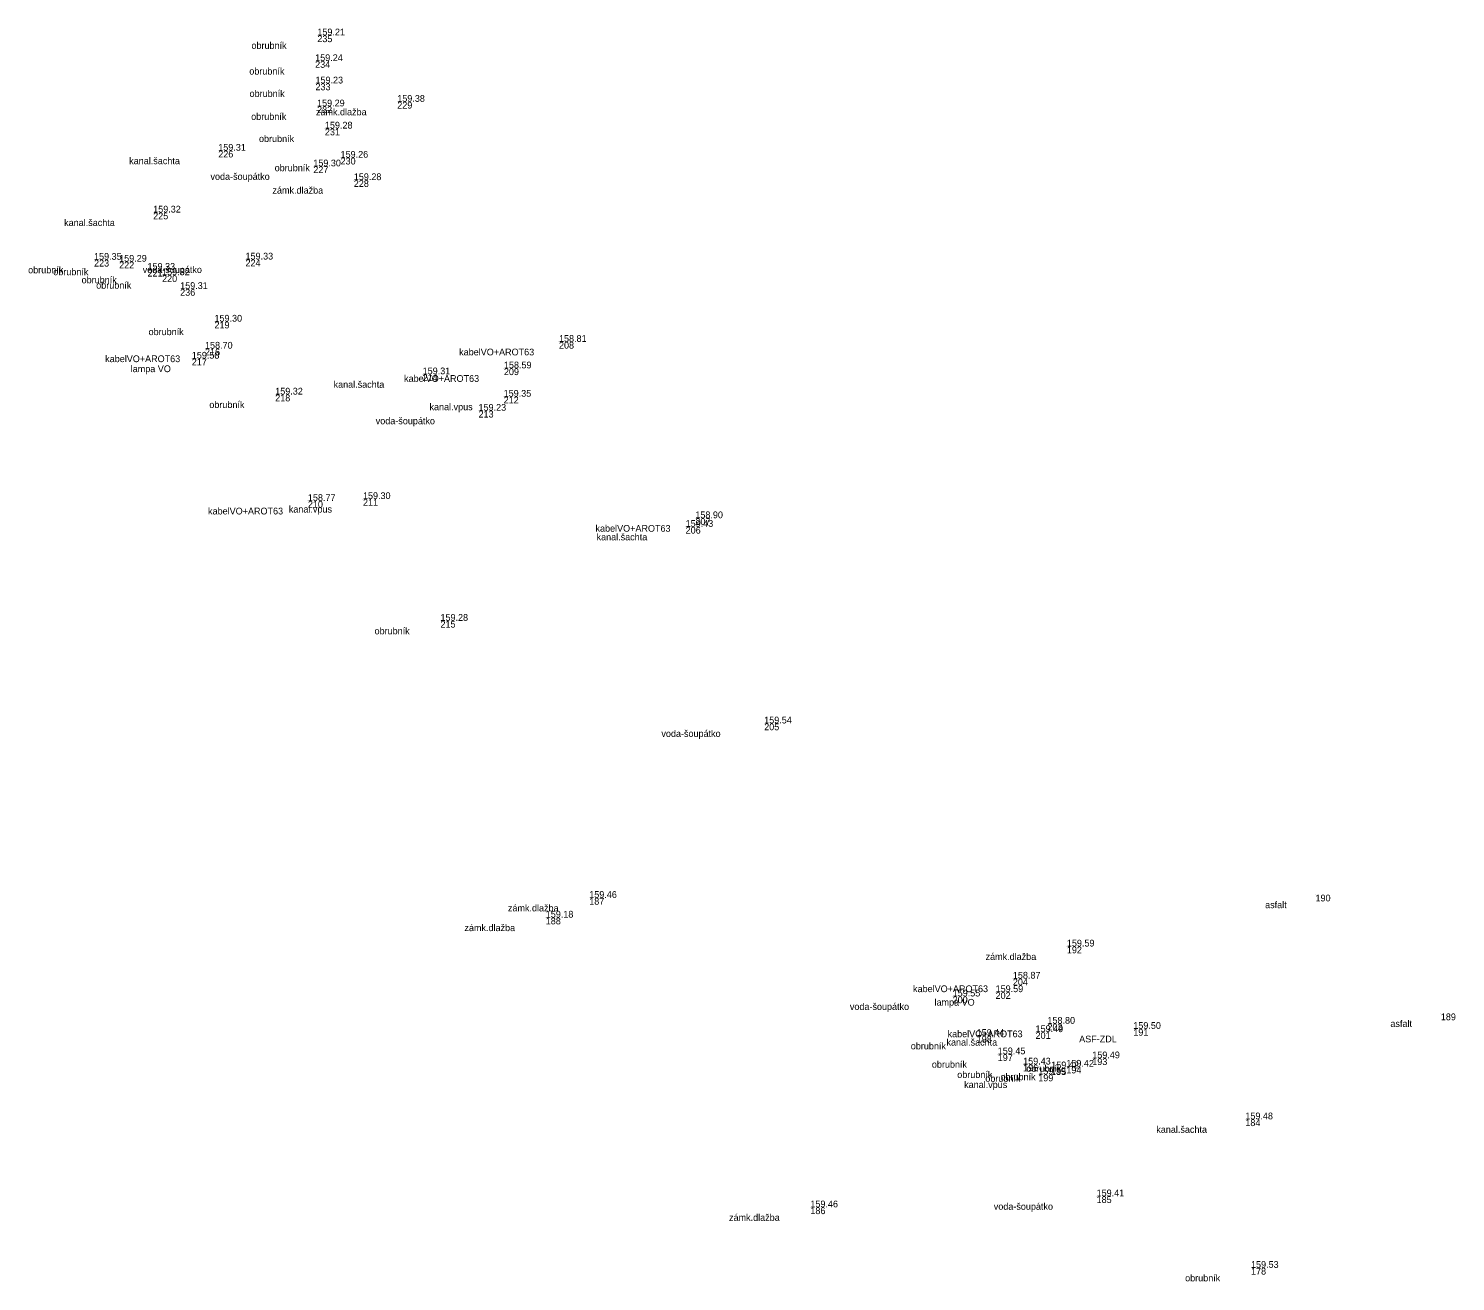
# Model space of a CAD drawing. Extents: x -583304 to -583163, y -1211038 to -1210841.
# Drawn here: x -583304.3 to -583251.4, y -1210887.3 to -1210840.9 of the extents above; entities that cross this region are included whole.
import ezdxf

# ---------------------------------------------------------------- set-up
doc = ezdxf.new("R2010")
doc.units = 0
for name, color, linetype in [('Vrstva 10', 7, 'Continuous'), ('Vrstva 7', 7, 'Continuous'), ('Vrstva 8', 7, 'Continuous'), ('Vrstva 9', 7, 'Continuous')]:
    doc.layers.add(name, color=color, linetype=linetype)

msp = doc.modelspace()

# ---------------------------------------------------------------- linework, layer by layer
at = {"layer": 'Vrstva 7'}
for p, q in [((-583293.57, -1210841.14), (-583293.57, -1210841.14)), ((-583293.65, -1210842.09), (-583293.65, -1210842.09)), ((-583293.64, -1210842.92), (-583293.64, -1210842.92)), ((-583290.61, -1210843.6), (-583290.61, -1210843.6)), ((-583293.58, -1210843.77), (-583293.58, -1210843.77)), ((-583293.29, -1210844.59), (-583293.29, -1210844.59)), ((-583297.24, -1210845.41), (-583297.24, -1210845.41)), ((-583292.71, -1210845.67), (-583292.71, -1210845.67)), ((-583293.72, -1210845.99), (-583293.72, -1210845.99)), ((-583292.22, -1210846.5), (-583292.22, -1210846.5)), ((-583299.65, -1210847.7), (-583299.65, -1210847.7)), ((-583296.23, -1210849.44), (-583296.23, -1210849.44)), ((-583301.84, -1210849.45), (-583301.84, -1210849.45)), ((-583300.91, -1210849.52), (-583300.91, -1210849.52)), ((-583299.86, -1210849.82), (-583299.86, -1210849.82)), ((-583299.32, -1210850.02), (-583299.32, -1210850.02)), ((-583298.65, -1210850.53), (-583298.65, -1210850.53)), ((-583297.38, -1210851.74), (-583297.38, -1210851.74)), ((-583284.62, -1210852.49), (-583284.62, -1210852.49)), ((-583298.22, -1210853.11), (-583298.22, -1210853.11)), ((-583297.73, -1210852.74), (-583297.73, -1210852.74)), ((-583286.66, -1210853.47), (-583286.66, -1210853.47)), ((-583289.67, -1210853.69), (-583289.67, -1210853.69)), ((-583295.13, -1210854.44), (-583295.13, -1210854.44)), ((-583286.67, -1210854.52), (-583286.67, -1210854.52)), ((-583287.6, -1210855.04), (-583287.6, -1210855.04)), ((-583293.92, -1210858.38), (-583293.92, -1210858.38)), ((-583291.88, -1210858.31), (-583291.88, -1210858.31)), ((-583279.93, -1210859.34), (-583279.93, -1210859.34)), ((-583279.57, -1210859.02), (-583279.57, -1210859.02)), ((-583289.01, -1210862.82), (-583289.01, -1210862.82)), ((-583277.02, -1210866.62), (-583277.02, -1210866.62)), ((-583283.5, -1210873.08), (-583283.5, -1210873.08)), ((-583256.6, -1210872.96), (-583256.6, -1210872.96)), ((-583285.11, -1210873.81), (-583285.11, -1210873.81)), ((-583265.81, -1210874.88), (-583265.81, -1210874.88)), ((-583267.81, -1210876.07), (-583267.81, -1210876.07)), ((-583270.04, -1210876.73), (-583270.04, -1210876.73)), ((-583268.45, -1210876.57), (-583268.45, -1210876.57)), ((-583251.96, -1210877.36), (-583251.96, -1210877.36)), ((-583266.53, -1210877.74), (-583266.53, -1210877.74)), ((-583263.35, -1210877.93), (-583263.35, -1210877.93)), ((-583269.15, -1210878.19), (-583269.15, -1210878.19)), ((-583266.97, -1210878.05), (-583266.97, -1210878.05)), ((-583268.37, -1210878.87), (-583268.37, -1210878.87)), ((-583264.87, -1210879.02), (-583264.87, -1210879.02)), ((-583267.43, -1210879.25), (-583267.43, -1210879.25)), ((-583266.39, -1210879.39), (-583266.39, -1210879.39)), ((-583265.83, -1210879.33), (-583265.83, -1210879.33)), ((-583266.87, -1210879.62), (-583266.87, -1210879.62)), ((-583259.2, -1210881.28), (-583259.2, -1210881.28)), ((-583264.71, -1210884.13), (-583264.71, -1210884.13)), ((-583275.31, -1210884.54), (-583275.31, -1210884.54)), ((-583258.99, -1210886.78), (-583258.99, -1210886.78))]:
    msp.add_line(p, q, dxfattribs=at)

# ---------------------------------------------------------------- texts
at = {"layer": 'Vrstva 10'}
for s, p in [('obrubník', (-583296.01, -1210841.64)), ('obrubník', (-583296.09, -1210842.59)), ('obrubník', (-583296.08, -1210843.42)), ('obrubník', (-583296.02, -1210844.27)), ('zámk.dlažba', (-583293.622, -1210844.1)), ('obrubník', (-583295.73, -1210845.09)), ('kanal.šachta', (-583300.538, -1210845.91)), ('voda-šoupátko', (-583297.527, -1210846.49)), ('obrubník', (-583295.15, -1210846.17)), ('zámk.dlažba', (-583295.232, -1210847)), ('kanal.šachta', (-583302.948, -1210848.2)), ('obrubník', (-583304.28, -1210849.95)), ('obrubník', (-583303.35, -1210850.02)), ('voda-šoupátko', (-583300.037, -1210849.94)), ('obrubník', (-583302.3, -1210850.32)), ('obrubník', (-583301.76, -1210850.52)), ('obrubník', (-583299.82, -1210852.24)), ('kabelVO+AROT63', (-583301.427, -1210853.24)), ('kabelVO+AROT63', (-583288.317, -1210852.99)), ('lampa VO', (-583300.482, -1210853.61)), ('kanal.šachta', (-583292.968, -1210854.19)), ('kabelVO+AROT63', (-583290.357, -1210853.97)), ('obrubník', (-583297.57, -1210854.94)), ('kanal.vpus', (-583289.416, -1210855.02)), ('voda-šoupátko', (-583291.407, -1210855.54)), ('kabelVO+AROT63', (-583297.617, -1210858.88)), ('kanal.vpus', (-583294.626, -1210858.81)), ('kabelVO+AROT63', (-583283.267, -1210859.52)), ('kanal.šachta', (-583283.228, -1210859.84)), ('obrubník', (-583291.45, -1210863.32)), ('voda-šoupátko', (-583280.827, -1210867.12)), ('asfalt', (-583258.468, -1210873.46)), ('zámk.dlažba', (-583286.512, -1210873.58)), ('zámk.dlažba', (-583288.122, -1210874.31)), ('zámk.dlažba', (-583268.822, -1210875.38)), ('kabelVO+AROT63', (-583271.507, -1210876.57)), ('lampa VO', (-583270.712, -1210877.07)), ('voda-šoupátko', (-583273.847, -1210877.23)), ('kabelVO+AROT63', (-583270.227, -1210878.24)), ('asfalt', (-583253.828, -1210877.86)), ('obrubník', (-583271.59, -1210878.69)), ('kanal.šachta', (-583270.268, -1210878.55)), ('ASF-ZDL', (-583265.354, -1210878.43)), ('obrubník', (-583270.81, -1210879.37)), ('obrubník', (-583269.87, -1210879.75)), ('obrubník', (-583268.27, -1210879.83)), ('obrubník', (-583267.31, -1210879.52)), ('kanal.vpus', (-583269.616, -1210880.12)), ('obrubník', (-583268.83, -1210879.89)), ('kanal.šachta', (-583262.498, -1210881.78)), ('zámk.dlažba', (-583278.322, -1210885.04)), ('voda-šoupátko', (-583268.517, -1210884.63)), ('obrubník', (-583261.43, -1210887.28))]:
    msp.add_text(s, height=0.25, dxfattribs=at).set_placement(p)
at = {"layer": 'Vrstva 8'}
for s, p in [('235', (-583293.57, -1210841.39)), ('234', (-583293.65, -1210842.34)), ('233', (-583293.64, -1210843.17)), ('229', (-583290.61, -1210843.85)), ('232', (-583293.58, -1210844.02)), ('231', (-583293.29, -1210844.84)), ('226', (-583297.24, -1210845.66)), ('230', (-583292.71, -1210845.92)), ('227', (-583293.72, -1210846.24)), ('228', (-583292.22, -1210846.75)), ('225', (-583299.65, -1210847.95)), ('224', (-583296.23, -1210849.69)), ('223', (-583301.84, -1210849.7)), ('222', (-583300.91, -1210849.77)), ('221', (-583299.86, -1210850.07)), ('220', (-583299.32, -1210850.27)), ('236', (-583298.65, -1210850.78)), ('219', (-583297.38, -1210851.99)), ('208', (-583284.62, -1210852.74)), ('217', (-583298.22, -1210853.36)), ('216', (-583297.73, -1210852.99)), ('209', (-583286.66, -1210853.72)), ('214', (-583289.67, -1210853.94)), ('218', (-583295.13, -1210854.69)), ('212', (-583286.67, -1210854.77)), ('213', (-583287.6, -1210855.29)), ('210', (-583293.92, -1210858.63)), ('211', (-583291.88, -1210858.56)), ('206', (-583279.93, -1210859.59)), ('207', (-583279.57, -1210859.27)), ('215', (-583289.01, -1210863.07)), ('205', (-583277.02, -1210866.87)), ('187', (-583283.5, -1210873.33)), ('190', (-583256.6, -1210873.21)), ('188', (-583285.11, -1210874.06)), ('192', (-583265.81, -1210875.13)), ('204', (-583267.81, -1210876.32)), ('200', (-583270.04, -1210876.98)), ('202', (-583268.45, -1210876.82)), ('189', (-583251.96, -1210877.61)), ('203', (-583266.53, -1210877.99)), ('191', (-583263.35, -1210878.18)), ('198', (-583269.15, -1210878.44)), ('201', (-583266.97, -1210878.3)), ('197', (-583268.37, -1210879.12)), ('193', (-583264.87, -1210879.27)), ('196', (-583267.43, -1210879.5)), ('195', (-583266.39, -1210879.64)), ('194', (-583265.83, -1210879.58)), ('199', (-583266.87, -1210879.87)), ('184', (-583259.2, -1210881.53)), ('185', (-583264.71, -1210884.38)), ('186', (-583275.31, -1210884.79)), ('178', (-583258.99, -1210887.03))]:
    msp.add_text(s, height=0.25, dxfattribs=at).set_placement(p)
at = {"layer": 'Vrstva 9'}
for s, p in [('159.21 ', (-583293.57, -1210841.14)), ('159.24 ', (-583293.65, -1210842.09)), ('159.23 ', (-583293.64, -1210842.92)), ('159.29 ', (-583293.58, -1210843.77)), ('159.38 ', (-583290.61, -1210843.6)), ('159.28 ', (-583293.29, -1210844.59)), ('159.31 ', (-583297.24, -1210845.41)), ('159.30 ', (-583293.72, -1210845.99)), ('159.26 ', (-583292.71, -1210845.67)), ('159.28 ', (-583292.22, -1210846.5)), ('159.32 ', (-583299.65, -1210847.7)), ('159.35 ', (-583301.84, -1210849.45)), ('159.29 ', (-583300.91, -1210849.52)), ('159.33 ', (-583296.23, -1210849.44)), ('159.33 ', (-583299.86, -1210849.82)), ('159.32 ', (-583299.32, -1210850.02)), ('159.31', (-583298.65, -1210850.53)), ('159.30 ', (-583297.38, -1210851.74)), ('158.70 ', (-583297.73, -1210852.74)), ('158.81 ', (-583284.62, -1210852.49)), ('159.58 ', (-583298.22, -1210853.11)), ('159.31 ', (-583289.67, -1210853.69)), ('158.59 ', (-583286.66, -1210853.47)), ('159.32 ', (-583295.13, -1210854.44)), ('159.35 ', (-583286.67, -1210854.52)), ('159.23 ', (-583287.6, -1210855.04)), ('158.77 ', (-583293.92, -1210858.38)), ('159.30 ', (-583291.88, -1210858.31)), ('158.90 ', (-583279.57, -1210859.02)), ('159.43 ', (-583279.93, -1210859.34)), ('159.28 ', (-583289.01, -1210862.82)), ('159.54 ', (-583277.02, -1210866.62)), ('159.46 ', (-583283.5, -1210873.08)), ('159.18 ', (-583285.11, -1210873.81)), ('159.59 ', (-583265.81, -1210874.88)), ('158.87 ', (-583267.81, -1210876.07)), ('159.59 ', (-583268.45, -1210876.57)), ('159.55 ', (-583270.04, -1210876.73)), ('159.44 ', (-583269.15, -1210878.19)), ('159.49 ', (-583266.97, -1210878.05)), ('158.80 ', (-583266.53, -1210877.74)), ('159.50 ', (-583263.35, -1210877.93)), ('159.45 ', (-583268.37, -1210878.87)), ('159.43 ', (-583267.43, -1210879.25)), ('159.49 ', (-583264.87, -1210879.02)), ('159.39 ', (-583266.87, -1210879.62)), ('159.42 ', (-583266.39, -1210879.39)), ('159.42 ', (-583265.83, -1210879.33)), ('159.48 ', (-583259.2, -1210881.28)), ('159.46 ', (-583275.31, -1210884.54)), ('159.41 ', (-583264.71, -1210884.13)), ('159.53 ', (-583258.99, -1210886.78))]:
    msp.add_text(s, height=0.25, dxfattribs=at).set_placement(p)

doc.saveas('drawing.dxf')
